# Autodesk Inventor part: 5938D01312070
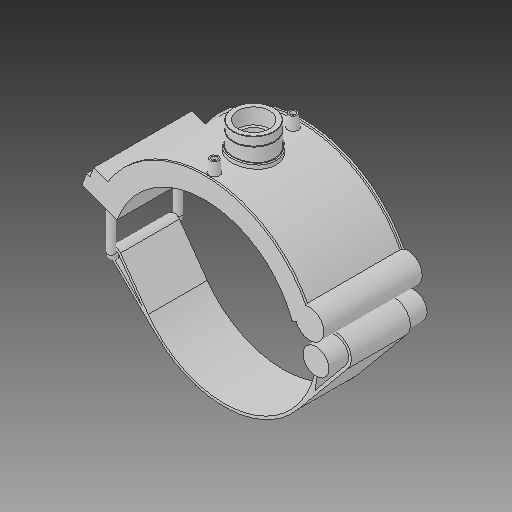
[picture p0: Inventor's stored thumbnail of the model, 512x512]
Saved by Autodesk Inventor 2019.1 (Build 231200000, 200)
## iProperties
Created: 2017-07
Part Number: 5938D01312070
Material: Generic
Description: PLASSON TRANSITION SADDLE 12''DIPS x 2"NPT
Document SubType Name: Modeling
Designer: KIM
Density: 1 g/cm^3
Appearance: Default
Author: KIM
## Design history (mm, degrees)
derived "5938D.ipt"
feature "Solid1::5938D.ipt"
tag "TaggingFeature1"
body "Solid1"
other parameters: "d_" = 333.8, "B_" = 194.818, "H_" = 46.736, "L_" = 176.022, "d_t" = 6, "G_" = 56.656, "d148" = 5.007, "d160" = 5.007, "d169" = 5.007, "d192" = 13.352, "d0" = 333.8, "d1" = 400.56, "d2" = 487.045, "d3" = 83.45, "d4" = 176.022, "d5" = 0, "d40" = 208.2912, "d41" = 79.3184, "d43" = 0, "d45" = 0, "d47" = 247.016, "d48" = 73.6528, "d50" = 0, "d78" = 222.28, "d79" = 15, "d80" = 70.4088, "d82" = 5 deg, "d84" = 4, "d85" = 14, "d86" = 0, "d87" = 3, "d88" = 0, "d96" = 408.5712, "d97" = 3.52044, "d98" = 0, "d102" = 1.69968, "d103" = 56.656, "d104" = 28.0416, "d105" = 0, "d106" = 45.3248, "d108" = 0, "d109" = -15.57867, "d111" = 0.5, "d112" = 0.5, "d113" = 0, "d114" = 0.5, "d117" = 0.56656, "d120" = 140 deg, "d121" = 24.228, "d122" = 20 deg, "d123" = 1602.24, "d124" = 240.336, "d126" = 0, "d143" = 343.814, "d145" = 51.35385, "d149" = 5.007, "d150" = 56.48923, "d153" = 176.022, "d154" = 0, "d156" = 200.28, "d157" = 160 deg, "d159" = 13.352, "d161" = 5.007, "d162" = 105.6132, "d163" = 0, "d164" = 166.9, "d167" = 33.38, "d168" = 195.39512, "d170" = 5.007, "d172" = 0, "d173" = 1, "d175" = 166.9, "d176" = 20 deg, "d177" = 23.366, "d178" = 66.76, "d180" = 0, "d183" = 26.704, "d184" = 18.6928, "d185" = 57.20715, "d186" = 57.20715, "d187" = 200.28, "d188" = 20.028, "d189" = 23.366, "d190" = 0, "d191" = 240.336, "d193" = 13.352, "d194" = 6.8429, "d195" = 90 deg, "d197" = 0, "d199" = 0
